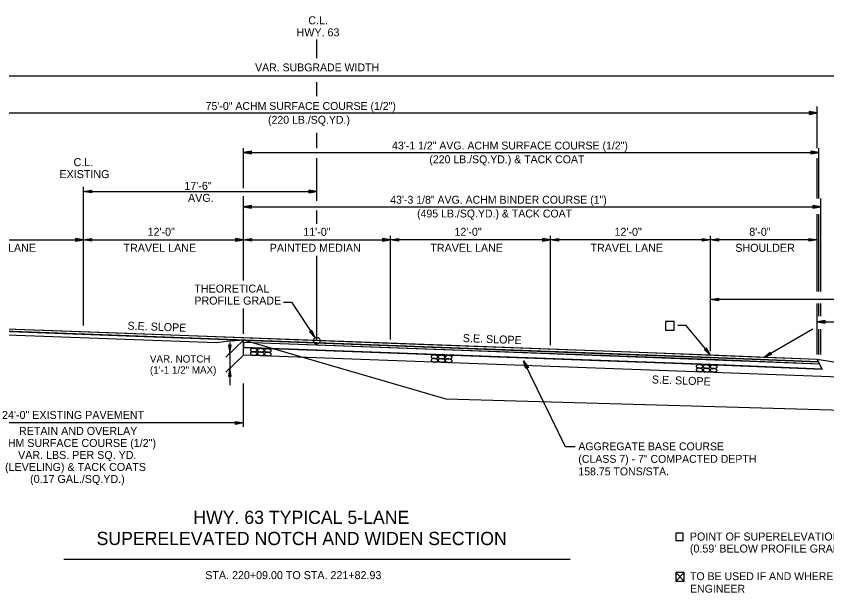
# Model space of a CAD drawing. Extents: x 1461846 to 1462006, y 1686171 to 1686805.
# Drawn here: x 1461902.5 to 1461963.2, y 1686494.2 to 1686537.4 of the extents above; entities that cross this region are included whole.
import ezdxf

# ---------------------------------------------------------------- set-up
doc = ezdxf.new("R2010")
doc.units = 0
for name, color, linetype in [('1', 7, 'Continuous'), ('10', 7, 'Continuous'), ('12', 7, 'Continuous'), ('19', 7, 'Continuous'), ('20', 7, 'Continuous'), ('3', 7, 'Continuous'), ('42', 7, 'Continuous'), ('R_Draft', 7, 'Continuous')]:
    doc.layers.add(name, color=color, linetype=linetype)

# ---------------------------------------------------------------- blocks, each defined once
blk = doc.blocks.new('ROCKS')
at = {"layer": '1'}
blk.add_spline([(0.013, 0.06), (0.053, 0.053), (0.107, 0.033), (0.133, 0.013), (0.133, -0.007), (0.12, -0.033), (0.107, -0.04), (0.073, -0.053), (0.033, -0.067), (0.013, -0.067), (-0.02, -0.06), (-0.06, -0.053), (-0.087, -0.047), (-0.113, -0.02), (-0.113, -0.007), (-0.107, 0.02), (-0.087, 0.033), (-0.067, 0.047), (-0.033, 0.053), (-0.02, 0.06), (0.013, 0.06)], degree=3, dxfattribs=at)

msp = doc.modelspace()

# ---------------------------------------------------------------- linework, layer by layer
at = {"layer": '10'}
for p, q in [((1461951.906, 1686495.75), (1461952.547, 1686495.109)), ((1461952.547, 1686495.75), (1461951.906, 1686495.109))]:
    msp.add_line(p, q, dxfattribs=at)
for points in [[(1461951.146, 1686513.914), (1461951.787, 1686513.914), (1461951.787, 1686514.555), (1461951.146, 1686514.555), (1461951.146, 1686513.914)], [(1461952.298, 1686495.109), (1461952.547, 1686495.109), (1461952.547, 1686495.75), (1461951.906, 1686495.75), (1461951.906, 1686495.109), (1461952.287, 1686495.109)]]:
    msp.add_lwpolyline(points, dxfattribs=at)
at = {"layer": '19'}
for p, q in [((1461925.014, 1686534.301), (1461925.014, 1686535.692)), ((1461925.014, 1686531.455), (1461925.014, 1686532.501)), ((1461925.014, 1686527.551), (1461925.014, 1686528.698)), ((1461925.014, 1686523.613), (1461925.014, 1686526.797)), ((1461907.514, 1686520.985), (1461907.514, 1686524.656)), ((1461925.014, 1686521.885), (1461925.014, 1686522.894)), ((1461918.588, 1686512.787), (1461918.378, 1686512.787)), ((1461918.378, 1686512.787), (1461918.483, 1686512.187)), ((1461918.433, 1686512.787), (1461918.468, 1686512.347)), ((1461918.483, 1686512.187), (1461918.588, 1686512.787)), ((1461918.498, 1686512.347), (1461918.538, 1686512.787)), ((1461919.514, 1686512.998), (1461919.514, 1686512.623)), ((1461943.63, 1686505.174), (1461940.495, 1686511.613)), ((1461940.672, 1686511.032), (1461940.495, 1686511.613)), ((1461940.495, 1686511.613), (1461940.859, 1686511.124)), ((1461940.716, 1686511.055), (1461940.552, 1686511.464)), ((1461940.578, 1686511.477), (1461940.81, 1686511.103)), ((1461962.514, 1686511.716), (1461962.876, 1686510.993)), ((1461918.483, 1686511.062), (1461918.378, 1686510.462)), ((1461918.468, 1686510.902), (1461918.428, 1686510.462)), ((1461918.588, 1686510.462), (1461918.483, 1686511.062)), ((1461918.533, 1686510.462), (1461918.498, 1686510.902)), ((1461940.859, 1686511.124), (1461940.672, 1686511.032)), ((1461962.876, 1686510.993), (1461962.684, 1686511.376)), ((1461962.684, 1686511.376), (1461962.684, 1686511.376)), ((1461962.876, 1686510.993), (1461962.876, 1686510.993)), ((1461918.378, 1686510.462), (1461918.588, 1686510.462)), ((1461944.367, 1686505.174), (1461943.63, 1686505.174))]:
    msp.add_line(p, q, dxfattribs=at)
for points in [[(1461887.432, 1686514.352), (1461891.238, 1686514.211), (1461911.417, 1686513.464), (1461930.555, 1686512.756), (1461938.176, 1686512.474), (1461948.934, 1686512.076), (1461954.677, 1686511.863), (1461956.599, 1686511.786), (1461962.599, 1686511.546), (1461962.599, 1686511.546), (1461962.599, 1686511.546), (1461962.514, 1686511.716), (1461962.514, 1686511.716), (1461962.514, 1686511.716), (1461956.649, 1686511.951), (1461948.529, 1686512.258), (1461938.2, 1686512.64), (1461930.551, 1686512.923), (1461911.463, 1686513.629), (1461891.292, 1686514.375), (1461887.514, 1686514.515)], [(1461962.684, 1686511.376), (1461954.514, 1686511.703), (1461919.514, 1686512.998), (1461919.514, 1686512.998), (1461919.514, 1686512.998), (1461919.514, 1686513.165), (1461919.514, 1686513.165), (1461919.514, 1686513.165), (1461954.494, 1686511.87), (1461962.599, 1686511.546)]]:
    msp.add_lwpolyline(points, close=True, dxfattribs=at)
for points in [[(1461962.684, 1686511.376), (1461962.684, 1686511.376), (1461962.684, 1686511.376), (1461935.845, 1686512.394), (1461919.514, 1686512.998)], [(1461919.514, 1686512.623), (1461935.824, 1686512.019), (1461953.05, 1686511.382), (1461962.876, 1686510.993), (1461962.876, 1686510.993), (1461962.876, 1686510.993)]]:
    msp.add_lwpolyline(points, dxfattribs=at)
at = {"layer": '20'}
for p, q in [((1461875.769, 1686532.965), (1461972.291, 1686532.965)), ((1461961.914, 1686530.3), (1461961.914, 1686530.09)), ((1461962.514, 1686530.195), (1461961.914, 1686530.3)), ((1461962.514, 1686527.551), (1461962.514, 1686530.686)), ((1461887.514, 1686530.195), (1461962.514, 1686530.195)), ((1461962.354, 1686530.21), (1461961.914, 1686530.245)), ((1461961.914, 1686530.09), (1461962.514, 1686530.195)), ((1461961.914, 1686530.14), (1461962.354, 1686530.18)), ((1461919.514, 1686524.55), (1461919.514, 1686527.551)), ((1461920.114, 1686527.337), (1461919.514, 1686527.232)), ((1461919.514, 1686527.232), (1461962.639, 1686527.232)), ((1461919.514, 1686527.232), (1461920.114, 1686527.127)), ((1461920.114, 1686527.282), (1461919.674, 1686527.247)), ((1461920.114, 1686527.127), (1461920.114, 1686527.337)), ((1461962.039, 1686527.337), (1461962.039, 1686527.127)), ((1461962.639, 1686527.232), (1461962.039, 1686527.337)), ((1461962.479, 1686527.247), (1461962.039, 1686527.282)), ((1461962.039, 1686527.127), (1461962.639, 1686527.232)), ((1461962.639, 1686523.782), (1461962.639, 1686527.551)), ((1461919.674, 1686527.217), (1461920.114, 1686527.177)), ((1461962.039, 1686527.177), (1461962.479, 1686527.217)), ((1461962.514, 1686523.782), (1461962.514, 1686526.801)), ((1461919.514, 1686520.985), (1461919.514, 1686523.965)), ((1461962.775, 1686516.811), (1461962.775, 1686523.782)), ((1461920.114, 1686523.27), (1461919.514, 1686523.165)), ((1461919.514, 1686523.165), (1461962.775, 1686523.165)), ((1461919.514, 1686523.165), (1461920.114, 1686523.06)), ((1461920.114, 1686523.215), (1461919.674, 1686523.18)), ((1461919.674, 1686523.15), (1461920.114, 1686523.11)), ((1461920.114, 1686523.06), (1461920.114, 1686523.27)), ((1461962.175, 1686523.27), (1461962.175, 1686523.06)), ((1461962.775, 1686523.165), (1461962.175, 1686523.27)), ((1461962.615, 1686523.18), (1461962.175, 1686523.215)), ((1461962.175, 1686523.06), (1461962.775, 1686523.165)), ((1461962.175, 1686523.11), (1461962.615, 1686523.15)), ((1461962.514, 1686520.985), (1461962.514, 1686522.6)), ((1461962.639, 1686516.811), (1461962.639, 1686522.6)), ((1461962.639, 1686514.951), (1461962.639, 1686515.911)), ((1461962.775, 1686514.951), (1461962.775, 1686515.911)), ((1461963.114, 1686514.637), (1461962.514, 1686514.532)), ((1461962.514, 1686514.532), (1461972.291, 1686514.532)), ((1461962.514, 1686514.532), (1461963.114, 1686514.427)), ((1461963.114, 1686514.582), (1461962.674, 1686514.547)), ((1461962.674, 1686514.517), (1461963.114, 1686514.477)), ((1461963.114, 1686514.427), (1461963.114, 1686514.637)), ((1461962.639, 1686512.1), (1461962.639, 1686513.977)), ((1461962.775, 1686512.1), (1461962.775, 1686513.977)), ((1461919.538, 1686513.187), (1461918.184, 1686511.894)), ((1461919.514, 1686512.04), (1461918.184, 1686510.769))]:
    msp.add_line(p, q, dxfattribs=at)
msp.add_lwpolyline([(1461918.483, 1686512.978), (1461918.483, 1686509.781)], dxfattribs=at)
at = {"layer": '3'}
msp.add_line((1461906.041, 1686496.751), (1461943.987, 1686496.751), dxfattribs=at)
at = {"layer": 'R_Draft'}
for p, q in [((1461907.509, 1686524.307), (1461908.109, 1686524.412)), ((1461908.109, 1686524.202), (1461907.509, 1686524.307)), ((1461907.514, 1686524.307), (1461925.014, 1686524.307)), ((1461907.669, 1686524.322), (1461908.109, 1686524.357)), ((1461908.109, 1686524.252), (1461907.669, 1686524.292)), ((1461908.109, 1686524.412), (1461908.109, 1686524.202)), ((1461924.414, 1686524.412), (1461924.414, 1686524.202)), ((1461925.014, 1686524.307), (1461924.414, 1686524.412)), ((1461924.854, 1686524.322), (1461924.414, 1686524.357)), ((1461924.414, 1686524.202), (1461925.014, 1686524.307)), ((1461924.414, 1686524.252), (1461924.854, 1686524.292)), ((1461895.514, 1686520.685), (1461907.514, 1686520.685)), ((1461906.914, 1686520.79), (1461906.914, 1686520.58)), ((1461907.514, 1686520.685), (1461906.914, 1686520.79)), ((1461907.354, 1686520.7), (1461906.914, 1686520.735)), ((1461906.914, 1686520.58), (1461907.514, 1686520.685)), ((1461906.914, 1686520.63), (1461907.354, 1686520.67)), ((1461907.514, 1686514.262), (1461907.514, 1686520.985)), ((1461907.514, 1686520.685), (1461908.114, 1686520.79)), ((1461907.514, 1686520.685), (1461919.514, 1686520.685)), ((1461908.114, 1686520.58), (1461907.514, 1686520.685)), ((1461907.674, 1686520.7), (1461908.114, 1686520.735)), ((1461908.114, 1686520.63), (1461907.674, 1686520.67)), ((1461908.114, 1686520.79), (1461908.114, 1686520.58)), ((1461918.914, 1686520.79), (1461918.914, 1686520.58)), ((1461919.514, 1686520.685), (1461918.914, 1686520.79)), ((1461919.354, 1686520.7), (1461918.914, 1686520.735)), ((1461918.914, 1686520.58), (1461919.514, 1686520.685)), ((1461918.914, 1686520.63), (1461919.354, 1686520.67)), ((1461919.514, 1686517.627), (1461919.514, 1686520.985)), ((1461919.514, 1686520.685), (1461920.114, 1686520.79)), ((1461920.114, 1686520.58), (1461919.514, 1686520.685)), ((1461919.514, 1686520.685), (1461930.514, 1686520.685)), ((1461919.674, 1686520.7), (1461920.114, 1686520.735)), ((1461920.114, 1686520.63), (1461919.674, 1686520.67)), ((1461920.114, 1686520.79), (1461920.114, 1686520.58)), ((1461929.914, 1686520.79), (1461929.914, 1686520.58)), ((1461930.514, 1686520.685), (1461929.914, 1686520.79)), ((1461930.354, 1686520.7), (1461929.914, 1686520.735)), ((1461929.914, 1686520.58), (1461930.514, 1686520.685)), ((1461929.914, 1686520.63), (1461930.354, 1686520.67)), ((1461930.514, 1686513.224), (1461930.514, 1686520.985)), ((1461930.514, 1686520.685), (1461931.114, 1686520.79)), ((1461931.114, 1686520.58), (1461930.514, 1686520.685)), ((1461942.514, 1686520.685), (1461930.514, 1686520.685)), ((1461930.674, 1686520.7), (1461931.114, 1686520.735)), ((1461931.114, 1686520.63), (1461930.674, 1686520.67)), ((1461931.114, 1686520.79), (1461931.114, 1686520.58)), ((1461941.914, 1686520.79), (1461941.914, 1686520.58)), ((1461942.514, 1686520.685), (1461941.914, 1686520.79)), ((1461942.354, 1686520.7), (1461941.914, 1686520.735)), ((1461941.914, 1686520.58), (1461942.514, 1686520.685)), ((1461941.914, 1686520.63), (1461942.354, 1686520.67)), ((1461942.514, 1686512.78), (1461942.514, 1686520.985)), ((1461942.514, 1686520.685), (1461943.114, 1686520.79)), ((1461954.514, 1686520.685), (1461942.514, 1686520.685)), ((1461943.114, 1686520.58), (1461942.514, 1686520.685)), ((1461942.674, 1686520.7), (1461943.114, 1686520.735)), ((1461943.114, 1686520.63), (1461942.674, 1686520.67)), ((1461943.114, 1686520.79), (1461943.114, 1686520.58)), ((1461953.914, 1686520.58), (1461953.914, 1686520.79)), ((1461953.914, 1686520.79), (1461954.514, 1686520.685)), ((1461953.914, 1686520.735), (1461954.354, 1686520.7)), ((1461954.514, 1686520.685), (1461953.914, 1686520.58)), ((1461954.354, 1686520.67), (1461953.914, 1686520.63)), ((1461954.514, 1686512.336), (1461954.514, 1686520.985)), ((1461954.514, 1686520.685), (1461955.114, 1686520.79)), ((1461962.514, 1686520.685), (1461954.514, 1686520.685)), ((1461955.114, 1686520.58), (1461954.514, 1686520.685)), ((1461954.674, 1686520.7), (1461955.114, 1686520.735)), ((1461955.114, 1686520.63), (1461954.674, 1686520.67)), ((1461955.114, 1686520.79), (1461955.114, 1686520.58)), ((1461961.914, 1686520.58), (1461961.914, 1686520.79)), ((1461961.914, 1686520.79), (1461962.514, 1686520.685)), ((1461961.914, 1686520.735), (1461962.354, 1686520.7)), ((1461962.514, 1686520.685), (1461961.914, 1686520.58)), ((1461962.354, 1686520.67), (1461961.914, 1686520.63)), ((1461962.514, 1686516.811), (1461962.514, 1686520.985)), ((1461925.014, 1686513.128), (1461925.014, 1686519.485)), ((1461954.514, 1686516.211), (1461955.114, 1686516.316)), ((1461955.114, 1686516.316), (1461955.114, 1686516.106)), ((1461984.514, 1686516.211), (1461954.514, 1686516.211)), ((1461955.114, 1686516.106), (1461954.514, 1686516.211)), ((1461954.674, 1686516.226), (1461955.114, 1686516.261)), ((1461955.114, 1686516.156), (1461954.674, 1686516.196)), ((1461962.514, 1686512.1), (1461962.514, 1686515.911)), ((1461919.514, 1686513.631), (1461919.514, 1686515.526)), ((1461924.638, 1686513.898), (1461924.464, 1686513.782)), ((1461924.804, 1686513.479), (1461924.596, 1686513.865)), ((1461924.883, 1686513.341), (1461924.638, 1686513.898)), ((1461924.464, 1686513.782), (1461924.883, 1686513.341)), ((1461924.504, 1686513.805), (1461924.781, 1686513.467)), ((1461919.514, 1686512.04), (1461919.514, 1686513.165)), ((1461954.216, 1686512.567), (1461954.055, 1686512.435)), ((1461954.055, 1686512.435), (1461954.514, 1686512.036)), ((1461954.092, 1686512.461), (1461954.401, 1686512.151)), ((1461954.422, 1686512.166), (1461954.178, 1686512.53)), ((1461954.514, 1686512.036), (1461954.216, 1686512.567)), ((1461958.514, 1686511.876), (1461958.984, 1686512.264)), ((1461959.088, 1686512.081), (1461958.514, 1686511.876)), ((1461958.646, 1686511.968), (1461959.009, 1686512.22)), ((1461959.061, 1686512.129), (1461958.661, 1686511.942)), ((1461958.984, 1686512.264), (1461959.088, 1686512.081)), ((1461962.514, 1686511.716), (1461954.514, 1686512.036)), ((1461962.599, 1686511.546), (1461954.514, 1686511.87)), ((1461954.684, 1686511.696), (1461954.514, 1686511.703)), ((1461962.684, 1686511.376), (1461954.514, 1686511.703)), ((1461984.514, 1686508.05), (1461962.514, 1686511.716)), ((1461954.876, 1686511.313), (1461954.514, 1686511.328)), ((1461962.876, 1686510.993), (1461954.514, 1686511.328)), ((1461919.514, 1686506.659), (1461919.514, 1686509.918)), ((1461919.514, 1686506.959), (1461895.514, 1686506.959)), ((1461918.914, 1686506.854), (1461918.914, 1686507.064)), ((1461918.914, 1686507.064), (1461919.514, 1686506.959)), ((1461918.914, 1686507.009), (1461919.354, 1686506.974)), ((1461919.514, 1686506.959), (1461918.914, 1686506.854)), ((1461919.354, 1686506.944), (1461918.914, 1686506.904))]:
    msp.add_line(p, q, dxfattribs=at)
for points in [[(1461922.512, 1686516.003), (1461923.112, 1686516.003), (1461924.883, 1686513.341)], [(1461951.787, 1686513.914), (1461951.787, 1686514.555), (1461951.146, 1686514.555), (1461951.146, 1686513.914), (1461951.787, 1686513.914)], [(1462004.832, 1686512.162), (1461984.872, 1686511.458), (1461970.134, 1686507.926), (1461968, 1686507.772), (1461963.59, 1686507.904), (1461955.708, 1686508.135), (1461934.695, 1686508.743), (1461919.514, 1686513.165), (1461918.223, 1686513.06), (1461917.452, 1686512.972), (1461899.751, 1686513.614), (1461895.514, 1686514.053), (1461888.778, 1686512.7), (1461874.437, 1686508.371)], [(1461954.514, 1686512.036), (1461925.014, 1686513.128), (1461895.514, 1686514.219)], [(1461909.514, 1686513.535), (1461895.514, 1686514.053)], [(1461954.514, 1686511.87), (1461925.014, 1686512.961), (1461895.514, 1686514.053)], [(1461952.071, 1686514.3), (1461952.641, 1686514.3), (1461954.514, 1686512.036)], [(1461962.175, 1686513.994), (1461958.514, 1686511.876)], [(1461954.514, 1686511.703), (1461919.514, 1686512.998)], [(1461954.514, 1686511.328), (1461919.514, 1686512.623)], [(1461954.514, 1686511.87), (1461933.514, 1686512.647)], [(1461972.291, 1686510.087), (1461919.514, 1686512.04)], [(1461952.466, 1686498.138), (1461952.466, 1686498.699), (1461951.906, 1686498.699), (1461951.906, 1686498.138), (1461952.466, 1686498.138)]]:
    msp.add_lwpolyline(points, dxfattribs=at)
msp.add_circle((1461925.009, 1686513.125), 0.25, dxfattribs=at)

# ---------------------------------------------------------------- block references
at = {"layer": '19', "xscale": 2.0611362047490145, "yscale": 2.0611362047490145, "rotation": -3.7637562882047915}
for p in [(1461920.255, 1686512.165), (1461920.256, 1686512.427), (1461920.784, 1686512.411), (1461920.784, 1686512.149), (1461921.314, 1686512.395), (1461921.314, 1686512.133), (1461933.807, 1686511.926), (1461934.336, 1686511.911), (1461934.865, 1686511.895), (1461933.807, 1686511.664), (1461934.336, 1686511.649), (1461934.865, 1686511.633), (1461953.668, 1686511.206), (1461953.668, 1686510.944), (1461954.196, 1686510.929), (1461954.197, 1686511.191), (1461954.726, 1686511.175), (1461954.726, 1686510.913)]:
    msp.add_blockref('ROCKS', p, dxfattribs=at)

# ---------------------------------------------------------------- texts
at = {"layer": '10'}
for s, p in [('VAR. NOTCH', (1461912.494, 1686511.483)), ('(1\'-1 1/2" MAX)', (1461912.494, 1686510.655))]:
    msp.add_text(s, height=0.55, dxfattribs=at).set_placement(p)
for s, height, rotation, p in [('STA. 220+09.00 TO STA. 221+82.93', 0.6, 359.99538, (1461916.638, 1686495.252)), ('TO BE USED IF AND WHERE DIRECTED BY THE ', 0.59001, 360, (1461952.979, 1686495.176)), ('ENGINEER', 0.59, 360, (1461952.979, 1686494.236))]:
    msp.add_text(s, height=height, rotation=rotation, dxfattribs=at).set_placement(p)
at = {"layer": '12'}
for s, p in [('HWY. 63 TYPICAL 5-LANE ', (1461915.746, 1686499.39)), ('SUPERELEVATED NOTCH AND WIDEN SECTION', (1461908.492, 1686497.806))]:
    msp.add_text(s, height=0.98999, rotation=359.99538, dxfattribs=at).set_placement(p)
at = {"layer": '19'}
for s, p in [('AGGREGATE BASE COURSE', (1461944.605, 1686504.909)), ('(CLASS 7) - 7" COMPACTED DEPTH ', (1461944.605, 1686503.969)), ('158.75 TONS/STA.', (1461944.605, 1686503.029))]:
    msp.add_text(s, height=0.59001, rotation=360, dxfattribs=at).set_placement(p)
at = {"layer": '42'}
for s, p in [('VAR. SUBGRADE WIDTH', (1461920.376, 1686533.314)), ('75\'-0" ACHM SURFACE COURSE (1/2")', (1461916.669, 1686530.42)), ('(220 LB./SQ.YD.)', (1461921.347, 1686529.387)), ('43\'-1 1/2" AVG. ACHM SURFACE COURSE (1/2")', (1461930.64, 1686527.457)), ('(220 LB./SQ.YD.) & TACK COAT', (1461933.439, 1686526.424)), ('43\'-3 1/8" AVG. ACHM BINDER COURSE (1")', (1461930.505, 1686523.393)), ('(495 LB./SQ.YD.) & TACK COAT', (1461932.519, 1686522.361))]:
    msp.add_text(s, height=0.59001, rotation=360, dxfattribs=at).set_placement(p)
at = {"layer": 'R_Draft'}
for s, rotation, p in [('C.L.', 360, (1461924.366, 1686536.837)), ('HWY. 63', 360, (1461923.487, 1686535.937)), ('17\'-6"', 360, (1461915.076, 1686524.43)), ('AVG.', 360, (1461915.348, 1686523.53)), ('S.E. SLOPE', 357.88102, (1461910.801, 1686513.954)), ('S.E. SLOPE', 357.88102, (1461935.937, 1686513.024)), ('S.E. SLOPE', 357.88102, (1461950.105, 1686509.923)), ('POINT OF SUPERELEVATION ROTATION', 359.99538, (1461952.966, 1686498.145)), ("(0.59' BELOW PROFILE GRADE)", 359.99538, (1461952.966, 1686497.245))]:
    msp.add_text(s, height=0.6, rotation=rotation, dxfattribs=at).set_placement(p)
for s, p in [('C.L.', (1461906.768, 1686526.209)), ('EXISTING', (1461905.712, 1686525.309)), ('12\'-0"', (1461912.317, 1686520.985)), ('11\'-0"', (1461923.987, 1686520.985)), ('12\'-0"', (1461935.317, 1686520.985)), ('12\'-0"', (1461947.317, 1686520.985)), ('8\'-0"', (1461957.416, 1686520.985)), ('TRAVEL LANE', (1461898.514, 1686519.785)), ('TRAVEL LANE', (1461910.514, 1686519.785)), ('PAINTED MEDIAN', (1461921.473, 1686519.785)), ('TRAVEL LANE', (1461933.514, 1686519.785)), ('TRAVEL LANE', (1461945.514, 1686519.785)), ('SHOULDER', (1461956.372, 1686519.785)), ('THEORETICAL', (1461915.821, 1686516.729)), ('PROFILE GRADE', (1461915.821, 1686515.829)), ('24\'-0" EXISTING PAVEMENT', (1461901.408, 1686507.259)), ('RETAIN AND OVERLAY', (1461902.676, 1686506.059)), ('ACHM SURFACE COURSE (1/2")', (1461900.716, 1686505.159)), ('VAR. LBS. PER SQ. YD.', (1461902.61, 1686504.259)), ('(LEVELING) & TACK COATS', (1461901.632, 1686503.359)), ('(0.17 GAL./SQ.YD.)', (1461903.513, 1686502.459))]:
    msp.add_text(s, height=0.6, dxfattribs=at).set_placement(p)

doc.saveas('drawing.dxf')
